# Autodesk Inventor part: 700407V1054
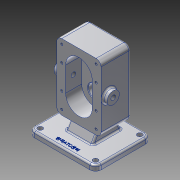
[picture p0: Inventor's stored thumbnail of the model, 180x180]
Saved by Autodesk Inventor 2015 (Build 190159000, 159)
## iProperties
Created: 2020-04
Part Number: 700407V1054
Material: 알루미늄 6061
Document SubType Name: Modeling
Designer: 1019876
Density: 2.7 g/cm^3
Appearance: 알루미늄 - 평지
Mass: 1470.94 g
Surface Area: 817.421 cm^2
Volume: 544.793 cm^3
Author: 1019876
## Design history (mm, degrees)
sketch "스케치1"
  geometry: L1 (60, -50)-(-60, -50); L2 (-60, -50)-(-60, 50); L3 (-60, 50)-(60, 50); L4 (60, 50)-(60, -50); L5 (60, -50)-(-60, 50); L6 (-60, -50)-(60, 50); 1 further point
  constraints: 12 end point, 2 midpoint, 2 parallel, 1 horizontal, 1 perpendicular
  dimensions: "d0" = 120 distance of L2.end L3.end; "d1" = 100 distance of L1.end L2.end
extrude "돌출1" new body sketch "스케치1" distance "d2" = 10; taper "d3" = 0 deg
sketch "스케치2"
  geometry: L1 (60, 50)-(-60, 50) reference; L2 (-24, -20)-(24, -20); L3 (24, -20)-(24, 33); L4 (24, 33)-(-24, 33); L5 (-24, 33)-(-24, -20); 1 further point
  constraints: 8 end point, 2 parallel, 1 horizontal, 1 perpendicular
  dimensions: "d4" = 17 distance between parallel lines of L1 L4; "d5" = 53 distance of L4.end L2.start; "d6" = 48 distance of L3.end L4.end; "d7" = 24 distance from line of L5 point (0, 0)
extrude "돌출2" join sketch "스케치2" distance "d8" = 70; taper "d9" = 0 deg
feature "면 기울기1" dims angle "d10" = 30 deg
node "작업 평면1"
sketch "스케치3"
  geometry: L1 (120, 0)-(120, -10) reference; L2 (120, -10)-(84, -10) reference; L3 (84, -10)-(36, -10) reference; L4 (36, -10)-(0, -10) reference; L5 (0, -10)-(0, 0) reference; L6 (0, 0)-(120, 0) reference; L7 (100, -150)-(20, -150); L8 (20, -150)-(20, -30); L9 (20, -30)-(100, -30); L10 (100, -30)-(100, -150); 1 further point
  constraints: 8 end point, 2 parallel, 1 horizontal, 1 perpendicular
  dimensions: "d12" = 150 distance between parallel lines of L6 L7; "d13" = 120 distance between parallel lines of L9 L7; "d14" = 80 distance of L7.start L7.end; "d15" = 40 distance from line of point (60, 0) L10
extrude "돌출3" join sketch "스케치3" distance "d16" = 53; taper "d17" = 0 deg
sketch "스케치4"
  geometry: L1 (100, 150)-(20, 150) reference; L2 (60, 44)-(60, 136); L3 (84, 68)-(84, 112); L4 (36, 112)-(36, 68); L5 (20, 150)-(20, 30) reference; A1 r 24 centre (60, 68) between (36, 68) and (84, 68); A2 r 24 centre (60, 112) between (84, 112) and (36, 112); 2 further points
  constraints: 8 end point, 6 point on circle, 4 tangent, 2 centre point, 2 point on line, 1 midpoint, 1 parallel, 1 vertical
  dimensions: "d18" = 92 distance of L2.start L2.end; "d19" = 24 radius of A2; "d20" = 60 distance from line of L1 point (60, 90); "d23" = 40 distance from line of L5 point (60, 90)
extrude "돌출4" cut sketch "스케치4" distance "d21" = 29; taper "d22" = 0 deg
sketch "스케치5"
  geometry: A1 r 24 centre (60, 112) between (84, 112) and (36, 112) reference; 1 further point
hole "구멍1" sketch "스케치5" at (60, 112) diameter "d24" = 17; stored, may be unused: countersink angle "d28" = 90 deg, drill point angle "d30" = 118 deg; dims "d25" = 6, "d26" = 25, "d27" = 15, "d29" = 8
sketch "스케치7"
  geometry: C1 r 8.5 at (60, -112) reference; C2 r 19 at (60, -112); 1 further point
  constraints: 1 centre point, 1 coincident
  dimensions: "d38" = 38 diameter of C2
extrude "돌출5" join sketch "스케치7" distance "d39" = 17; taper "d40" = 0 deg
sketch "스케치8"
  geometry: C1 r 8.5 at (0, 0) reference; 1 further point
hole "구멍3" sketch "스케치8" at (0, 0) diameter "d41" = 28; stored, may be unused: countersink angle "d45" = 90 deg, drill point angle "d47" = 0 deg; dims "d42" = 6, "d43" = 25, "d44" = 15, "d46" = 7.3
sketch "스케치9"
  geometry: C1 r 12.5 at (60, 68); A1 r 24 centre (60, 68) between (36, 68) and (84, 68) reference; 1 further point
  constraints: 1 centre point, 1 coincident
  dimensions: "d48" = 25 diameter of C1
extrude "돌출6" cut sketch "스케치9" distance "d49" = 15; taper "d50" = 0 deg
node "작업 평면2"
sketch "스케치10"
  geometry: L1 (150, 17)-(150, -83) reference; L2 (120, -53)-(0, -53) reference; C1 r 11 at (60, -39); 1 further point
  constraints: 1 centre point
  dimensions: "d52" = 90 distance from line of L1 C1.centre; "d53" = 14 distance from line of L2 C1.centre; "d54" = 22 diameter of C1
extrude "돌출7" join sketch "스케치10" stored distance "d55" = 15; taper "d56" = 0 deg
sketch "스케치11"
  geometry: C1 r 11 at (0, 0) reference; 1 further point
hole "구멍4" sketch "스케치11" at (0, 0) diameter "d57" = 8.376; stored, may be unused: countersink angle "d61" = 90 deg, drill point angle "d63" = 118 deg; dims "d58" = 26, "d59" = 25, "d60" = 15, "d62" = 33.3
fillet "모깎기1" dims "d64" = 9
sketch "스케치12"
  geometry: A1 r 9 centre (29, 39) between (20, 39) and (29, 30) reference; A2 r 9 centre (29, 141) between (29, 150) and (20, 141) reference; 3 further points
  constraints: 2 vertical alignment
  dimensions: "d65" = 29 distance of A2.centre point (29, 112); "d66" = 73 distance of point (29, 68) A2.centre
hole "구멍5" sketch "스케치12" at (29, 112), (29, 68), (29, 141), (29, 39) diameter "d67" = 4.134; stored, may be unused: countersink angle "d71" = 90 deg, drill point angle "d73" = 118 deg; dims "d68" = 10, "d69" = 25, "d70" = 15, "d72" = 12
fillet "모깎기2" dims "d74" = 10
sketch "스케치13"
  geometry: A1 r 10 centre (-50, 40) between (-50, 50) and (-60, 40) reference; A2 r 10 centre (-50, -40) between (-60, -40) and (-50, -50) reference; A3 r 10 centre (50, -40) between (50, -50) and (60, -40) reference; A4 r 10 centre (50, 40) between (60, 40) and (50, 50) reference; 1 further point
hole "구멍6" sketch "스케치13" at (50, 40), (-50, 40), (50, -40), (-50, -40) diameter "d75" = 9; stored, may be unused: countersink angle "d79" = 90 deg, drill point angle "d81" = 118 deg; dims "d76" = 10, "d77" = 25, "d78" = 15, "d80" = 12
sketch "스케치14"
  geometry: L1 (-60, 40)-(-60, -40) reference; L2 (-50, -50)-(50, -50) reference; 2 further points
  constraints: 1 other
  dimensions: "d82" = 60 distance from line of L1 point (0, -40); "d83" = 10 distance from line of L2 point (0, -40)
feature "엠보싱1" sketch "스케치14" dims "d0" = 120, "d1" = 100, "d84" = 0.5, "d85" = 0
chamfer "모따기1" distance "d86" = 0.7; stored, may be unused: second distance "d87" = 2, angle "d88" = 30 deg
fillet "모깎기3" dims "d89" = 0.5
chamfer "모따기2" distance "d90" = 1; stored, may be unused: second distance "d91" = 2, angle "d92" = 30 deg
fillet "모깎기4" dims "d93" = 3
fillet "모깎기5" dims "d94" = 3
fillet "모깎기6" dims "d95" = 3
fillet "모깎기7" dims "d96" = 3
node "솔리드1"
mirror "대칭1"
mirror "대칭2"
node "절단 모서리 투영1"
other parameters: "d11" = -17, "d51" = 8
